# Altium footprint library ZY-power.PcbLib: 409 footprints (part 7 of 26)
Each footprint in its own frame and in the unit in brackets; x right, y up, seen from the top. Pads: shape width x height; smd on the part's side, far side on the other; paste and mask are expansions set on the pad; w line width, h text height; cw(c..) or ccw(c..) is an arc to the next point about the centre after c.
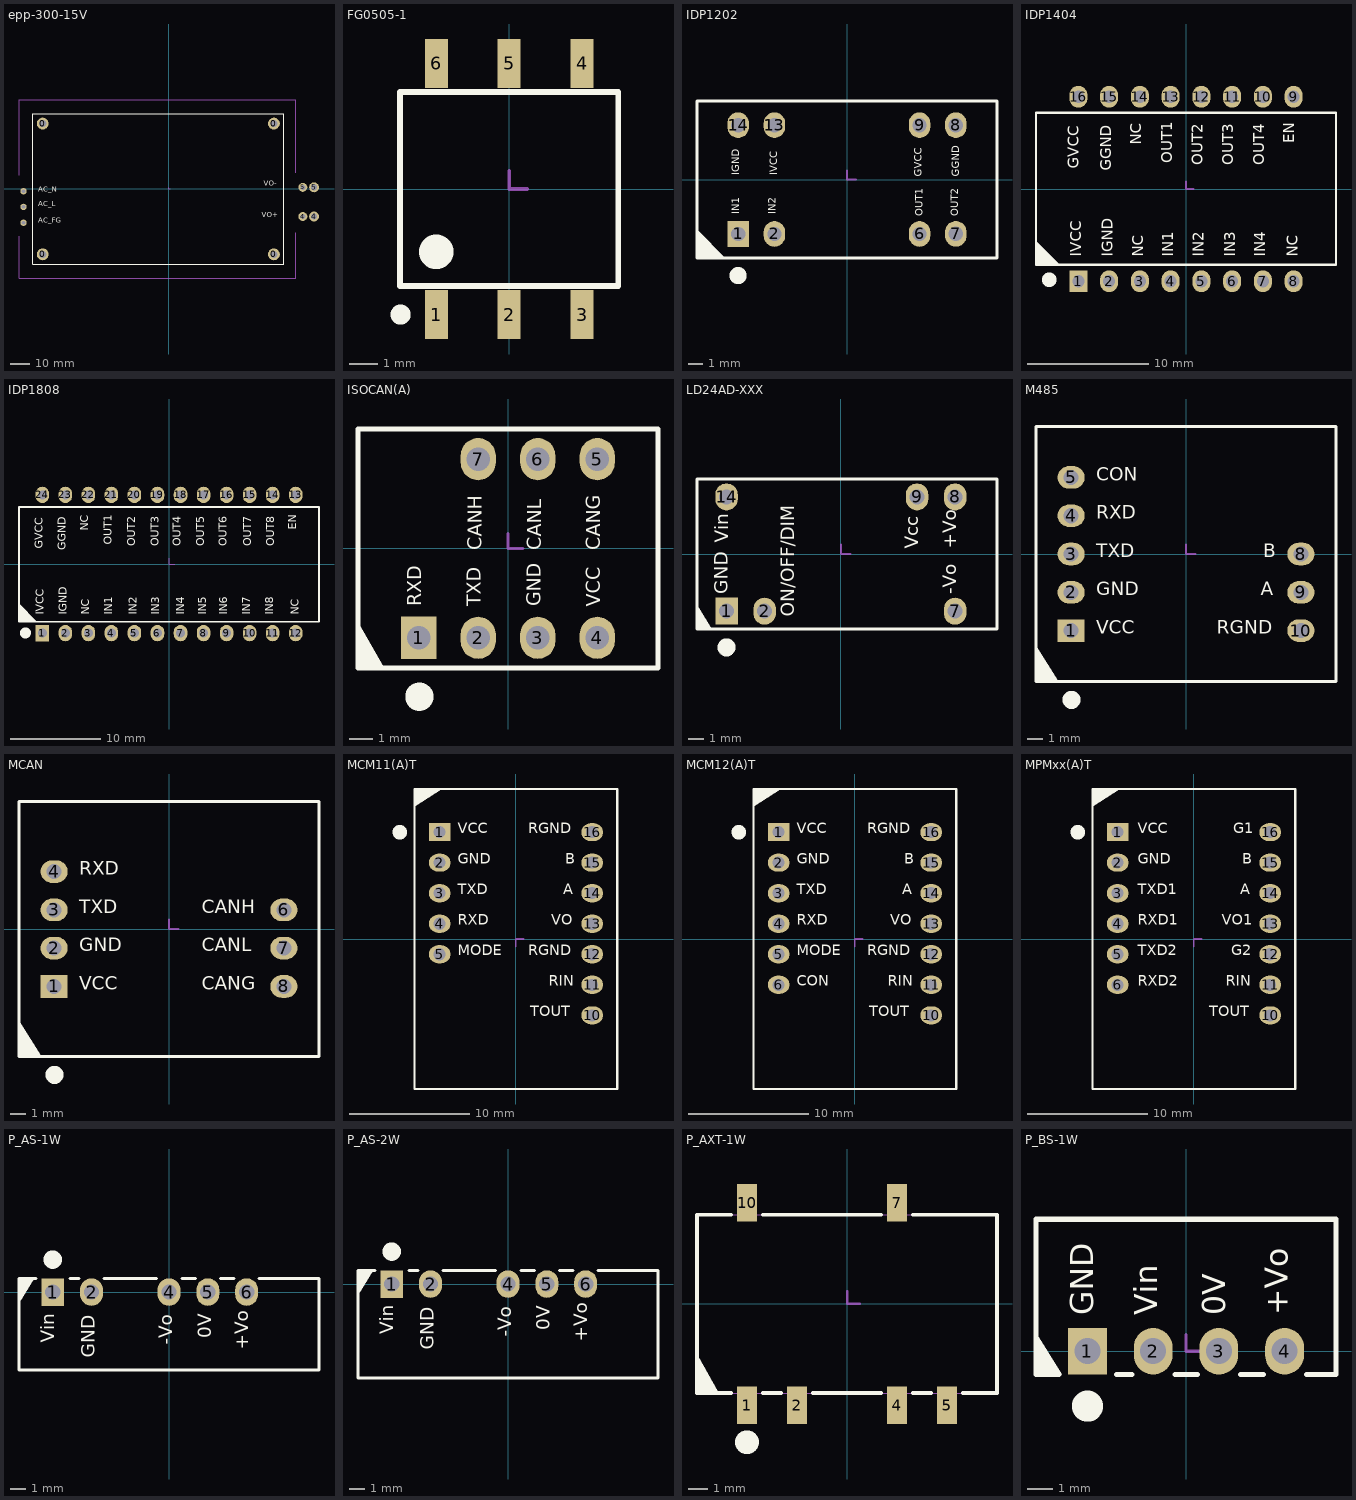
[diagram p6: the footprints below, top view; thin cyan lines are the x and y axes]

## epp-300-15V [mm]
height 22
pads (11):
  round 6 hole 3.6: 0(-63.785,-33.1) 0(-63.785,33.1) 0(53.215,-33.1) 0(53.215,33.1)
  round 3.2 hole 1.8: 1(-73.516,-1.134) 2(-73.516,-9.08) 3(-73.516,-17.076)
  round 4.5 hole 2.5: 4(67.846,-13.956) 5(67.846,0.813)
  round 5 hole 3.2: 4(73.516,-13.95) 5(73.516,0.825)
Top Overlay:
  lines w0.2: -68.785,-38.1 -68.785,38.1 58.215,38.1 58.215,-38.1 -68.785,-38.1
  text "AC_L" at -65.938,-9.779 h4.5
  text "AC_N" at -65.938,-2.311 h4.5
  text "AC_FG" at -65.938,-18.11 h4.5
  text "VO-" at 48.022,0.508 h4.5
  text "VO+" at 47.117,-15.367 h4.5
Mechanical 15:
  lines w0.127: 0,0.635 0,0 0.635,0
  lines w0.203: -75.785,-45.1 -75.785,-23.9 ; -75.785,6.875 -75.785,12.15 ; -75.785,11.7 -75.785,25.875 ; -75.785,25.675 -75.785,45.025 ; -75.785,45.05 -47.735,45.05 -33.56,45.05 64.191,45.05 ; -75.735,-45.1 -56.06,-45.1 -41.885,-45.1 64.191,-45.1 64.191,-22.175 ; 64.191,8.2 64.191,24.575 ; 64.191,24.275 64.191,45.026

## FG0505-1 [mm]
height 5.25
pads (6):
  rect 0.8x1.7 smd: 1(-2.54,-4.375) 2(0,-4.375) 3(2.54,-4.375) 4(2.54,4.375) 5(0,4.375) 6(-2.54,4.375)
Top Overlay:
  circle w1: c-2.54,-2.189 r0.1
  circle w0.5: c-3.783,-4.375 r0.1
  lines w0.2: -3.8,-3.375 -3.8,3.375 3.8,3.375 3.8,-3.375 -3.8,-3.375
Mechanical 15:
  lines w0.127: 0,0.635 0,0 0.635,0

## IDP1202 [mm] "20x10x8mm"
height 8.001
pads (8):
  rect 1.5x1.8 hole 1: 1(-7.62,-3.81)
  oval 1.5x1.8 hole 1: 2(-5.08,-3.81) 6(5.08,-3.81) 7(7.62,-3.802) 8(7.62,3.81) 9(5.08,3.81) 13(-5.08,3.81) 14(-7.62,3.81)
Top Overlay:
  circle w1: c-7.62,-6.725 r0.1
  region: -10.5,-5.5 -8.525,-5.5 -10.5,-3.525
  lines w0.2: -10.5,-5.5 10.5,-5.5 10.5,5.5 -10.5,5.5 -10.5,-5.5
  text "IGND" at -7.366,0.305 h0.89
  text "IVCC" at -4.724,0.305 h0.89
  text "GVCC" at 5.41,0.178 h0.89
  text "GGND" at 8.026,0.178 h0.89
  text "OUT2" at 7.976,-2.565 h0.89
  text "OUT1" at 5.461,-2.565 h0.89
  text "IN1" at -7.366,-2.413 h0.89
  text "IN2" at -4.826,-2.413 h0.89
Mechanical 15:
  lines w0.127: 0,0.635 0,0 0.635,0

## IDP1404 [mm] "23.97x14.41x9.65mm"
height 9.652
pads (16):
  rect 1.5x1.8 hole 1: 1(-8.89,-7.62)
  oval 1.5x1.8 hole 1: 2(-6.35,-7.62) 3(-3.81,-7.62) 4(-1.27,-7.62) 5(1.27,-7.62) 6(3.81,-7.62) 7(6.35,-7.62) 8(8.89,-7.62) 9(8.89,7.62) 10(6.35,7.62) 11(3.81,7.62) 12(1.27,7.62) 13(-1.27,7.62) 14(-3.81,7.62) 15(-6.35,7.62) 16(-8.89,7.62)
Top Overlay:
  circle w1: c-11.303,-7.499 r0.1
  region: -12.39,-6.274 -10.415,-6.274 -12.39,-4.299
  lines w0.2: -12.39,-6.274 -12.39,6.299 12.39,6.299 12.39,-6.274 -12.39,-6.274
  text "GVCC" at -8.509,1.655 h1.52
  text "GGND" at -5.842,1.524 h1.52
  text "NC" at -3.378,3.655 h1.52
  text "OUT4" at 6.782,1.962 h1.52
  text "OUT3" at 4.216,1.959 h1.52
  text "OUT2" at 1.702,1.968 h1.52
  text "OUT1" at -0.813,2.147 h1.52
  text "EN" at 9.271,3.791 h1.52
  text "NC" at 9.576,-5.588 h1.52
  text "IN4" at 6.883,-5.588 h1.52
  text "IN3" at 4.394,-5.588 h1.52
  text "IN2" at 1.778,-5.588 h1.52
  text "IN1" at -0.737,-5.588 h1.52
  text "NC" at -3.2,-5.588 h1.52
  text "IGND" at -5.74,-5.588 h1.52
  text "IVCC" at -8.331,-5.588 h1.52
Mechanical 15:
  lines w0.127: 0,0.635 0,0 0.635,0

## IDP1808 [mm] "32.32x14.41x6.7(9.65)mm"
height 6.248
pads (24):
  rect 1.5x1.8 hole 1: 1(-13.97,-7.62)
  oval 1.5x1.8 hole 1: 2(-11.43,-7.62) 3(-8.89,-7.62) 4(-6.35,-7.62) 5(-3.81,-7.62) 6(-1.27,-7.62) 7(1.27,-7.62) 8(3.81,-7.62) 9(6.35,-7.62) 10(8.89,-7.62) 11(11.43,-7.62) 12(13.97,-7.62) 13(13.97,7.62) 14(11.43,7.62) 15(8.89,7.62) 16(6.35,7.62) 17(3.81,7.62) 18(1.27,7.62) 19(-1.27,7.62) 20(-3.81,7.62) 21(-6.35,7.62) 22(-8.89,7.62) 23(-11.43,7.62) 24(-13.97,7.62)
Top Overlay:
  circle w1: c-15.834,-7.6 r0.1
  region: -16.54,-6.375 -14.565,-6.375 -16.54,-4.401
  lines w0.2: -16.54,-6.375 -16.54,6.299 16.54,6.299 16.54,-6.375 -16.54,-6.375
  text "NC" at -8.56,3.655 h1.52
  text "GGND" at -11.049,1.524 h1.52
  text "GVCC" at -13.589,1.655 h1.52
  text "OUT8" at 11.913,1.956 h1.52
  text "OUT7" at 9.423,1.959 h1.52
  text "OUT6" at 6.706,1.959 h1.52
  text "OUT5" at 4.242,1.952 h1.52
  text "OUT4" at 1.651,1.962 h1.52
  text "OUT3" at -0.813,1.959 h1.52
  text "OUT2" at -3.404,1.968 h1.52
  text "OUT1" at -5.969,2.147 h1.52
  text "EN" at 14.376,3.791 h1.52
  text "NC" at 14.656,-5.588 h1.52
  text "IN8" at 11.811,-5.588 h1.52
  text "IN7" at 9.296,-5.588 h1.52
  text "IN6" at 6.756,-5.588 h1.52
  text "IN5" at 4.42,-5.588 h1.52
  text "IN4" at 2.007,-5.588 h1.52
  text "IN3" at -0.737,-5.588 h1.52
  text "IN2" at -3.251,-5.588 h1.52
  text "IN1" at -5.918,-5.588 h1.52
  text "NC" at -8.484,-5.588 h1.52
  text "IGND" at -10.947,-5.588 h1.52
  text "IVCC" at -13.487,-5.588 h1.52
Mechanical 15:
  lines w0.127: 0,0.635 0,0 0.635,0

## ISOCAN(A) [mm]
height 7.7
pads (7):
  rect 1.5x1.8 hole 1: 1(-3.81,-3.81)
  oval 1.5x1.8 hole 1: 2(-1.27,-3.81) 3(1.27,-3.81) 4(3.81,-3.81) 5(3.81,3.81) 6(1.27,3.81) 7(-1.27,3.81)
Top Overlay:
  circle w1: c-3.783,-6.325 r0.1
  region: -5.284,-5.1 -6.4,-3.161 -6.4,-5.1
  lines w0.2: -6.4,-5.1 6.4,-5.1 6.4,5.1 -6.4,5.1 -6.4,-5.1
  text "RXD" at -3.491,-2.459 h1.02
  text "TXD" at -0.94,-2.459 h1.02
  text "GND" at 1.6,-2.459 h1.02
  text "VCC" at 4.14,-2.485 h1.02
  text "CANH" at -0.914,-0.072 h1.02
  text "CANL" at 1.64,-0.072 h1.02
  text "CANG" at 4.14,-0.072 h1.02
Mechanical 15:
  lines w0.127: 0,0.635 0,0 0.635,0

## LD24AD-XXX [mm]
pads (6):
  rect 1.5x1.8 hole 1: 1(-7.62,-3.81)
  oval 1.5x1.8 hole 1: 2(-5.08,-3.81) 7(7.62,-3.81) 8(7.62,3.81) 9(5.08,3.81) 14(-7.62,3.81)
Top Overlay:
  circle w1: c-7.62,-6.225 r0.1
  region: -9.59,-3.414 -9.59,-5 -8.596,-5
  lines w0.2: -9.59,-5 10.41,-5 10.41,5 -9.59,5 -9.59,-5
  text "ON/OFF/DIM" at -2.794,-4.191 h1.52
  text "Vin" at -7.223,0.762 h1.52
  text "GND" at -7.239,-2.667 h1.52
  text "Vcc" at 5.461,0.339 h1.52
  text "+Vo" at 8.001,0.338 h1.52
  text "-Vo" at 8.001,-2.667 h1.52
Mechanical 15:
  lines w0.127: 0,0.635 0,0 0.635,0

## M485 [mm]
height 7.1
pads (8):
  rect 1.8x1.5 hole 1: 1(-7.62,-5.08)
  oval 1.8x1.5 hole 1: 2(-7.62,-2.54) 3(-7.62,0) 4(-7.62,2.54) 5(-7.62,5.08) 8(7.62,0) 9(7.62,-2.54) 10(7.62,-5.08)
Top Overlay:
  circle w1: c-7.593,-9.675 r0.1
  region: -9.95,-6.12 -9.95,-8.45 -8.49,-8.45
  lines w0.2: -9.95,-8.45 -9.95,8.45 9.95,8.45 9.95,-8.45 -9.95,-8.45
  text "RGND" at 2.032,-5.588 h1.52
  text "A" at 4.952,-3.048 h1.52
  text "B" at 5.126,-0.508 h1.52
  text "CON" at -5.939,4.572 h1.52
  text "RXD" at -5.939,2.032 h1.52
  text "TXD" at -5.939,-0.508 h1.52
  text "VCC" at -5.938,-5.588 h1.52
  text "GND" at -5.939,-3.048 h1.52
Mechanical 15:
  lines w0.127: 0,0.635 0,0 0.635,0

## MCAN [mm]
height 7.1
pads (7):
  rect 1.8x1.5 hole 1: 1(-7.62,-3.81)
  oval 1.8x1.5 hole 1: 2(-7.62,-1.27) 3(-7.62,1.27) 4(-7.62,3.81) 6(7.62,1.27) 7(7.62,-1.27) 8(7.62,-3.81)
Top Overlay:
  circle w1: c-7.593,-9.675 r0.1
  region: -9.95,-6.12 -9.95,-8.45 -8.49,-8.45
  lines w0.2: -9.95,-8.45 -9.95,8.45 9.95,8.45 9.95,-8.45 -9.95,-8.45
  text "VCC" at -5.938,-4.318 h1.52
  text "RXD" at -5.939,3.302 h1.52
  text "TXD" at -5.939,0.762 h1.52
  text "GND" at -5.939,-1.778 h1.52
  text "CANH" at 2.189,0.762 h1.52
  text "CANL" at 2.189,-1.778 h1.52
  text "CANG" at 2.189,-4.318 h1.52
Mechanical 15:
  lines w0.127: 0,0.635 0,0 0.635,0

## MCM11(A)T [mm]
height 7.1
pads (12):
  rect 1.8x1.5 hole 1: 1(-6.35,8.89)
  oval 1.8x1.5 hole 1: 2(-6.35,6.35) 3(-6.35,3.81) 4(-6.35,1.27) 5(-6.35,-1.27) 10(6.35,-6.35) 11(6.35,-3.81) 12(6.35,-1.27) 13(6.35,1.27) 14(6.35,3.81) 15(6.35,6.35) 16(6.35,8.89)
Top Overlay:
  circle w1: c-9.675,8.89 r0.1
  region: -6.12,12.49 -8.45,12.49 -8.45,11.03
  lines w0.2: -8.45,-12.49 8.45,-12.49 8.45,12.49 -8.45,12.49 -8.45,-12.49
  text "VCC" at -4.826,8.509 h1.52
  text "GND" at -4.827,5.969 h1.52
  text "TXD" at -4.827,3.429 h1.52
  text "RXD" at -4.827,0.889 h1.52
  text "TOUT" at 1.2,-6.731 h1.52
  text "RIN" at 2.719,-4.191 h1.52
  text "RGND" at 1.016,-1.651 h1.52
  text "VO" at 2.945,0.889 h1.52
  text "A" at 3.936,3.429 h1.52
  text "B" at 4.11,5.969 h1.52
  text "RGND" at 1.016,8.509 h1.52
  text "MODE" at -4.827,-1.651 h1.52
Mechanical 15:
  lines w0.127: 0,-0.635 0,0 0.635,0

## MCM12(A)T [mm]
height 7.1
pads (13):
  rect 1.8x1.5 hole 1: 1(-6.35,8.89)
  oval 1.8x1.5 hole 1: 2(-6.35,6.35) 3(-6.35,3.81) 4(-6.35,1.27) 5(-6.35,-1.27) 6(-6.35,-3.81) 10(6.35,-6.35) 11(6.35,-3.81) 12(6.35,-1.27) 13(6.35,1.27) 14(6.35,3.81) 15(6.35,6.35) 16(6.35,8.89)
Top Overlay:
  circle w1: c-9.675,8.89 r0.1
  region: -6.12,12.49 -8.45,12.49 -8.45,11.03
  lines w0.2: -8.45,-12.49 8.45,-12.49 8.45,12.49 -8.45,12.49 -8.45,-12.49
  text "VCC" at -4.826,8.509 h1.52
  text "GND" at -4.827,5.969 h1.52
  text "TXD" at -4.827,3.429 h1.52
  text "RXD" at -4.827,0.889 h1.52
  text "TOUT" at 1.2,-6.731 h1.52
  text "RIN" at 2.719,-4.191 h1.52
  text "RGND" at 1.016,-1.651 h1.52
  text "VO" at 2.945,0.889 h1.52
  text "A" at 3.936,3.429 h1.52
  text "B" at 4.11,5.969 h1.52
  text "RGND" at 1.016,8.509 h1.52
  text "CON" at -4.827,-4.191 h1.52
  text "MODE" at -4.827,-1.651 h1.52
Mechanical 15:
  lines w0.127: 0,-0.635 0,0 0.635,0

## MPMxx(A)T [mm]
height 7.1
pads (13):
  rect 1.8x1.5 hole 1: 1(-6.35,8.89)
  oval 1.8x1.5 hole 1: 2(-6.35,6.35) 3(-6.35,3.81) 4(-6.35,1.27) 5(-6.35,-1.27) 6(-6.35,-3.81) 10(6.35,-6.35) 11(6.35,-3.81) 12(6.35,-1.27) 13(6.35,1.27) 14(6.35,3.81) 15(6.35,6.35) 16(6.35,8.89)
Top Overlay:
  circle w1: c-9.675,8.89 r0.1
  region: -6.12,12.49 -8.45,12.49 -8.45,11.03
  lines w0.2: -8.45,-12.49 -8.45,12.49 8.45,12.49 8.45,-12.49 -8.45,-12.49
  text "TXD2" at -4.7,-1.651 h1.52
  text "RXD2" at -4.7,-4.191 h1.52
  text "G1" at 3.28,8.509 h1.52
  text "B" at 4.037,5.969 h1.52
  text "A" at 3.864,3.429 h1.52
  text "VO1" at 2.303,0.889 h1.52
  text "G2" at 3.101,-1.651 h1.52
  text "RIN" at 2.647,-4.191 h1.52
  text "TOUT" at 1.255,-6.731 h1.52
  text "RXD1" at -4.7,0.889 h1.52
  text "TXD1" at -4.7,3.429 h1.52
  text "GND" at -4.7,5.969 h1.52
  text "VCC" at -4.699,8.509 h1.52
Mechanical 15:
  lines w0.127: 0,-0.635 0,0 0.635,0

## P_AS-1W [mm]
height 10.16
pads (5):
  rect 1.5x1.8 hole 1: 1(-7.62,0)
  oval 1.5x1.8 hole 1: 2(-5.08,0) 4(0,0) 5(2.54,0) 6(5.08,0)
Top Overlay:
  circle w1: c-7.62,2.125 r0.1
  region: -9.83,-0.686 -9.83,0.9 -8.836,0.9
  lines w0.2: -8.72,0.9 -9.83,0.9 -9.83,-5.1 9.82,-5.1 9.82,0.9 5.9,0.9 ; -6.5,0.9 -5.9,0.9 ; -4.26,0.9 -0.82,0.9 ; 0.846,0.9 1.72,0.9 ; 3.386,0.9 4.26,0.9
  text "+Vo" at 5.491,-3.772 h1.52
  text "-Vo" at 0.508,-3.462 h1.52
  text "GND" at -4.572,-4.318 h1.52
  text "Vin" at -7.239,-3.304 h1.52
  text "0V" at 3.048,-3.034 h1.52
Mechanical 15:
  lines w0.127: 0,0.635 0,0 0.635,0
3D body "zhenjao01.stp": height 8.36, standoff -4.08, extent 4.38,-1.48 5.78,0.12
3D body "zhenjao01.stp": height 8.36, standoff -4.08, extent 1.84,-1.48 3.24,0.12
3D body "zhenjao01.stp": height 8.36, standoff -4.08, extent -0.7,-1.48 0.7,0.12
3D body "zhenjao01.stp": height 8.36, standoff -4.08, extent -5.78,-1.48 -4.38,0.12
3D body "zhenjao01.stp": height 8.36, standoff -4.08, extent -8.32,-1.48 -6.92,0.12
3D body: height 10.16, standoff 0, extent -9.83,-5.1 9.82,0.9

## P_AS-2W [mm]
height 10.16
pads (5):
  rect 1.5x1.8 hole 1: 1(-7.62,0)
  oval 1.5x1.8 hole 1: 2(-5.08,0) 4(0,0) 5(2.54,0) 6(5.08,0)
Top Overlay:
  circle w1: c-7.62,2.125 r0.1
  region: -9.83,-0.686 -9.83,0.9 -8.836,0.9
  lines w0.2: -8.72,0.9 -9.83,0.9 -9.83,-6.15 9.82,-6.15 9.82,0.9 5.9,0.9 ; -6.5,0.9 -5.9,0.9 ; -4.26,0.9 -0.82,0.9 ; 0.846,0.9 1.72,0.9 ; 3.386,0.9 4.26,0.9
  text "+Vo" at 5.491,-3.772 h1.52
  text "-Vo" at 0.508,-3.462 h1.52
  text "GND" at -4.572,-4.318 h1.52
  text "Vin" at -7.239,-3.304 h1.52
  text "0V" at 3.028,-3.034 h1.52
Mechanical 15:
  lines w0.127: 0,0.635 0,0 0.635,0
3D body: height 10.16, standoff 0, extent -9.83,-6.15 9.82,0.9
3D body "zhenjao01.stp": height 8.36, standoff -4.08, extent -8.32,-1.48 -6.92,0.12
3D body "zhenjao01.stp": height 8.36, standoff -4.08, extent -5.78,-1.48 -4.38,0.12
3D body "zhenjao01.stp": height 8.36, standoff -4.08, extent -0.7,-1.48 0.7,0.12
3D body "zhenjao01.stp": height 8.36, standoff -4.08, extent 1.84,-1.48 3.24,0.12
3D body "zhenjao01.stp": height 8.36, standoff -4.08, extent 4.38,-1.48 5.78,0.12

## P_AXT-1W [mm]
height 7.25
pads (6):
  rect 1x1.9 smd: 1(-5.08,-5.15) 2(-2.54,-5.15) 4(2.54,-5.15) 5(5.08,-5.15) 7(2.54,5.15) 10(-5.08,5.15)
Top Overlay:
  circle w1: c-5.082,-7.023 r0.1
  region: -6.504,-4.53 -7.62,-2.591 -7.62,-4.53
  lines w0.2: -5.893,-4.53 -7.62,-4.53 -7.62,4.53 -5.893,4.53 ; -4.267,-4.53 -3.354,-4.53 ; -4.267,4.53 1.727,4.53 ; -1.726,-4.53 1.727,-4.53 ; 3.353,-4.53 4.266,-4.53 ; 3.353,4.53 7.62,4.53 7.62,-4.53 5.893,-4.53
Mechanical 15:
  lines w0.051: -7.62,-4.53 -7.62,4.53 7.62,4.53 7.62,-4.53 -7.62,-4.53
  lines w0.127: 0,0.635 0,0 0.635,0

## P_BS-1W [mm]
height 10.16
pads (4):
  rect 1.5x1.8 hole 1: 1(-3.81,0)
  oval 1.5x1.8 hole 1: 2(-1.27,0) 3(1.27,0) 4(3.81,0)
Top Overlay:
  circle w1: c-3.81,-2.125 r0.1
  region: -5.8,0.686 -5.8,-0.889 -4.813,-0.889
  lines w0.2: -4.91,-0.9 -5.8,-0.9 -5.8,5.1 5.8,5.1 5.8,-0.9 4.656,-0.9 ; -2.69,-0.9 -2.09,-0.9 ; -0.424,-0.9 0.45,-0.9 ; 2.116,-0.9 2.99,-0.9
  text "GND" at -3.302,1.396 h1.52
  text "Vin" at -0.813,1.397 h1.52
  text "0V" at 1.803,1.396 h1.52
  text "+Vo" at 4.216,1.396 h1.52
Mechanical 15:
  lines w0.127: 0,0.635 0,0 0.635,0
3D body "zhenjao01.stp": height 8.36, standoff -4.08, extent 3.11,-0.12 4.51,1.48
3D body "zhenjao01.stp": height 8.36, standoff -4.08, extent 0.57,-0.12 1.97,1.48
3D body "zhenjao01.stp": height 8.36, standoff -4.08, extent -1.97,-0.12 -0.57,1.48
3D body: height 10.16, standoff 0, extent -5.8,-0.9 5.8,5.1
3D body "zhenjao01.stp": height 8.36, standoff -4.08, extent -4.51,-0.12 -3.11,1.48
